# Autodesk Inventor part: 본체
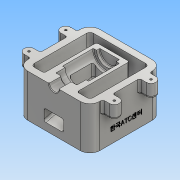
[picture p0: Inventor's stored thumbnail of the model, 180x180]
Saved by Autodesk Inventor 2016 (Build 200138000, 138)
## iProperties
Created: 2018-01
Part Number: 본체
Material: 알루미늄 6061
Document SubType Name: Modeling
Designer: Administrator
Density: 2.7 g/cm^3
Appearance: 알루미늄 - 평지
Mass: 994.887 g
Surface Area: 835.115 cm^2
Volume: 368.477 cm^3
Author: Administrator
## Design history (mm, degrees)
sketch "스케치1"
  geometry: L1 (-55, -55)-(55, -55); L2 (55, -55)-(55, 55); L3 (55, 55)-(-55, 55); L4 (-55, 55)-(-55, -55); L5 (-55, -55)-(55, 55); L6 (55, -55)-(-55, 55); 1 further point
  constraints: 12 end point, 2 midpoint, 2 parallel, 1 horizontal, 1 perpendicular
  dimensions: "d0" = 110 distance of L3.end L2.end; "d1" = 110 distance of L2.end L1.end
extrude "돌출1" new body sketch "스케치1" distance "d2" = 65; taper "d3" = 0 deg
sketch "스케치2"
  geometry: L1 (-55, -55)-(55, -55) reference; L2 (55, -55)-(55, 55) reference; L3 (55, 55)-(-55, 55) reference; L4 (-55, 55)-(-55, -55) reference; L5 (-45, 45)-(45, 45); L6 (45, 45)-(45, -45); L7 (45, -45)-(-45, -45); L8 (-45, -45)-(-45, 45); 1 further point
  constraints: 8 end point, 3 other
  dimensions: "d4" = 10 distance between parallel lines of L3 L5
extrude "돌출2" cut sketch "스케치2" stored distance "d5" = 65; taper "d6" = 0 deg
sketch "스케치3"
  geometry: L1 (55, -55)-(55, 55) reference; L2 (55, 55)-(-55, 55) reference; L3 (0, 0)-(0, 91.556); L4 (0, 0)-(113.572, 0); L5 (55, 35.5)-(65, 35.5); L6 (65, 35.5)-(65, 20.5); L7 (65, 20.5)-(55, 20.5); L8 (55, 20.5)-(55, 35.5); L9 (55, -20.5)-(55, -35.5); L10 (65, -35.5)-(65, -20.5); L11 (65, -20.5)-(55, -20.5); L12 (55, -35.5)-(65, -35.5); L13 (-65, -20.5)-(-55, -20.5); L14 (-55, 35.5)-(-65, 35.5); L15 (-65, 20.5)-(-55, 20.5); L16 (-55, 20.5)-(-55, 35.5); L17 (-65, 35.5)-(-65, 20.5); L18 (-55, -35.5)-(-65, -35.5); L19 (-65, -35.5)-(-65, -20.5); L20 (-55, -20.5)-(-55, -35.5); A1 r 7.5 centre (65, 28) between (65, 20.5) and (65, 35.5); A2 r 7.5 centre (65, -28) between (65, -35.5) and (65, -20.5); A3 r 7.5 centre (-65, 28) between (-65, 35.5) and (-65, 20.5); A4 r 7.5 centre (-65, -28) between (-65, -20.5) and (-65, -35.5)
  constraints: 36 end point, 15 symmetric about line, 8 point on circle, 4 centre point, 2 horizontal, 2 parallel, 1 midpoint, 1 perpendicular, 1 point on line, 1 vertical, 3 other
  dimensions: "d7" = 10 distance between parallel lines of L6 L1; "d8" = 27 distance from line of L2 A1.centre; "d9" = 7.5 radius of A1
extrude "돌출3" join sketch "스케치3" distance "d10" = 20; taper "d11" = 0 deg
sketch "스케치4"
  geometry: L1 (-45, 65)-(-45, 0) reference; L2 (-45, 8.564)-(35, 30); L3 (35, 30)-(35, 65); L4 (45, 0)-(-45, 0) reference; L5 (55, 0)-(55, 65) reference; L6 (-45, 65)-(45, 65) reference; 1 further point
  constraints: 4 end point, 2 point on line, 1 parallel
  dimensions: "d12" = 105 deg angle of L2 L1; "d13" = 30 distance from line of L4 L2.end; "d14" = 20 distance between parallel lines of L5 L3
extrude "돌출4" join sketch "스케치4" stored distance "d15" = 50; taper "d16" = 0 deg
sketch "스케치5"
  geometry: L1 (-55, -55)-(55, -55) reference; L2 (55, 55)-(-55, 55) reference; L3 (0, 0)-(0, 68.089); L4 (0, -45)-(0, 30); L5 (-15, 30)-(-15, 25); L6 (-15, 25)-(-20, 25); L7 (-20, 25)-(-20, -22); L8 (-20, -22)-(-16, -22); L9 (-16, -22)-(-16, -36); L10 (-16, -36)-(-7.5, -36); L11 (-7.5, -36)-(-7.5, -45); L12 (-45, -45)-(45, -45) reference; L13 (-15, 30)-(0, 30); L14 (-7.5, -45)-(-7.5, -55); L15 (0, -55)-(0, -45); L16 (0, -55)-(-7.5, -55)
  constraints: 26 end point, 8 perpendicular, 3 point on line, 2 midpoint, 1 collinear, 1 parallel, 1 vertical
  dimensions: "d17" = 15 diameter of L11 L3; "d18" = 32 diameter of L9 L3; "d19" = 40 diameter of L7 L3; "d20" = 30 diameter of L5 L3; "d21" = 19 distance between parallel lines of L1 L10; "d22" = 14 distance between parallel lines of L8 L10; "d23" = 47 distance between parallel lines of L6 L8; "d24" = 5 distance between parallel lines of L6 L13
revolve "회전1" sketch "스케치5" stored, may be unused: angle "d25" = 90 deg
sketch "스케치7"
  geometry: L1 (35, 30)-(-45, 8.564) reference; L2 (20, 31.157)-(-55, 11.061); L3 (-17, 39.243)-(-55, 29.061); L4 (-55, 0)-(-55, 65) reference; L5 (20, 31.157)-(20, 45); L6 (25, 45)-(-22, 45) reference; L7 (-17, 39.243)-(-17, 45); L8 (-22, 65)-(-22, 49) reference; L9 (-17, 45)-(20, 45); 1 further point
  constraints: 10 end point, 4 point on line, 3 parallel, 1 collinear, 1 vertical
  dimensions: "d29" = 5 distance between parallel lines of L1 L2; "d31" = 18 distance of L3.end L2.end; "d32" = 37 distance between parallel lines of L5 L7; "d33" = 5 distance between parallel lines of L8 L7
extrude "돌출5" cut sketch "스케치7" stored distance "d34" = 30; taper "d35" = 0 deg
sketch "스케치6"
  geometry: L1 (-20, 25)-(-15, 25) reference; L2 (-15, 20)-(15, 20); L3 (15, 20)-(15, -17); L4 (15, -17)-(-15, -17); L5 (-15, -17)-(-15, 20); 2 further points
  constraints: 8 end point, 2 parallel, 1 horizontal, 1 midpoint, 1 perpendicular, 1 vertical alignment
  dimensions: "d26" = 30 distance between parallel lines of L3 L5; "d27" = 37 distance between parallel lines of L4 L2; "d28" = 5 distance between parallel lines of L2 L1
extrude "돌출6" cut sketch "스케치6" stored distance "d36" = 30; taper "d37" = 0 deg
sketch "스케치8"
  geometry: L1 (0, 0)-(-65, 0) reference; L2 (0, 0)-(0, 110) reference; 2 further points
  constraints: 1 other
  dimensions: "d38" = 55 distance from line of L1 point (-20, 55); "d39" = 20 distance from line of L2 point (-20, 55)
feature "엠보싱1" sketch "스케치8" dims "d40" = 0.5, "d41" = 0
hole "구멍1" diameter "d44" = 3.242; stored, may be unused: countersink angle "d48" = 90 deg, drill point angle "d50" = 118 deg; dims "d42" = 10, "d43" = 10, "d45" = 9, "d46" = 4, "d47" = 2, "d49" = 11
fillet "모깎기1" dims "d57" = 15, "d58" = 5, "d59" = 3
chamfer "모따기1" distance "d60" = 1; stored, may be unused: second distance "d61" = 2, angle "d62" = 45 deg
fillet "모깎기2" dims "d63" = 1, "d64" = 3
fillet "모깎기3" dims "d65" = 3
node "솔리드1"
pattern_linear "직사각형 패턴1" dims "d53" = 56
